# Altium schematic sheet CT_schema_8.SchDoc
size 254 x 194 mm
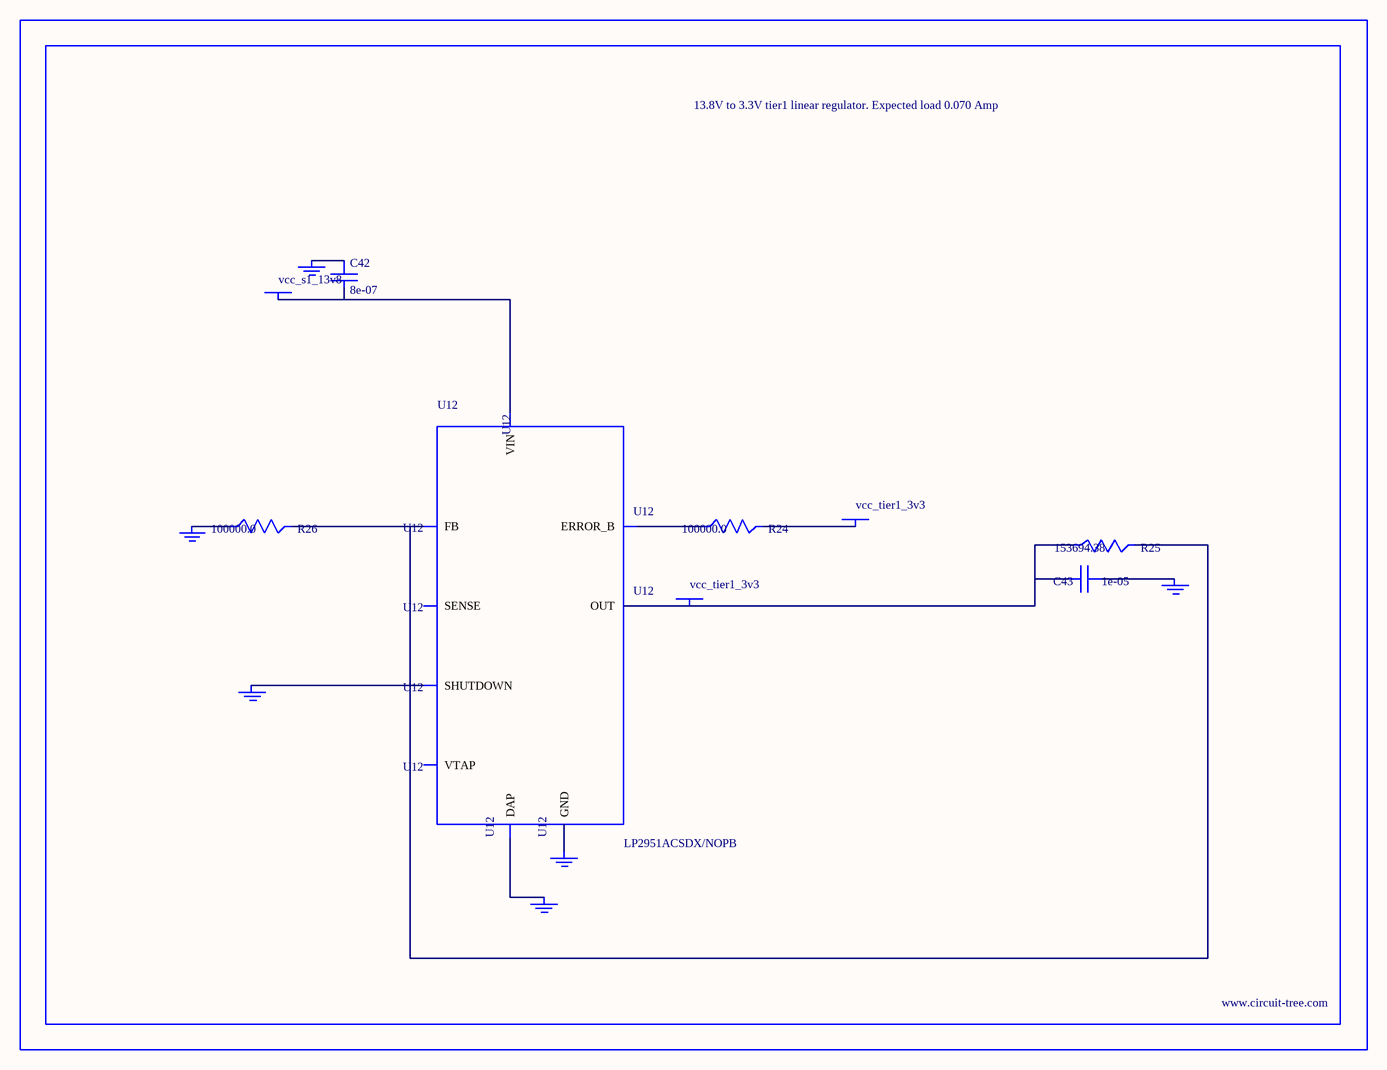
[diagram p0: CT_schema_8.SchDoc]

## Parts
BORDER7  (no value)
C42  8e-07  [R0603]
C43  1e-05  [C1210]
GND_INSTANCE_7_0  (no value)
GND_INSTANCE_7_1  (no value)
GND_INSTANCE_7_2  (no value)
GND_INSTANCE_7_3  (no value)
GND_INSTANCE_7_4  (no value)
GND_INSTANCE_7_5  (no value)
POWER_INSTANCE_7_0  vcc_tier1_3v3
POWER_INSTANCE_7_1  vcc_s1_13v8
POWER_INSTANCE_7_2  vcc_tier1_3v3
R24  100000.0  [R0603]
R25  153694.38  [R0603]
R26  100000.0  [R0603]
U12  LP2951ACSDX/NOPB  [WSON-8]

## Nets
NetC42_1: C42.1 GND_INSTANCE_7_3.0(GND)
NetC42_2: C42.2 POWER_INSTANCE_7_1.0(PWR) U12.8(VIN)
NetC43_1: C43.1 GND_INSTANCE_7_0.0(GND)
NetC43_2: C43.2 POWER_INSTANCE_7_2.0(PWR) R25.1 U12.1(OUT)
NetGND_INSTANCE_7_1_0: GND_INSTANCE_7_1.0(GND) U12.3(SHUTDOWN)
NetGND_INSTANCE_7_2_0: GND_INSTANCE_7_2.0(GND) R26.1
NetGND_INSTANCE_7_4_0: GND_INSTANCE_7_4.0(GND) U12.PAD(DAP)
NetGND_INSTANCE_7_5_0: GND_INSTANCE_7_5.0(GND) U12.4(GND)
NetPOWER_INSTANCE_7_0_0: POWER_INSTANCE_7_0.0(PWR) R24.2
NetR24_1: R24.1 U12.5(ERROR_B)
NetR25_2: R25.2 R26.2 U12.7(FB)

Not connected (* = marked no-connect by the designer): U12 2(SENSE) 6(VTAP)

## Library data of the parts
BORDER7 = BORDER_PAGE7
C42 = C42
C43 = GRM32DR61E106MA12L
GND_INSTANCE_7_0-GND_INSTANCE_7_5 = GND
POWER_INSTANCE_7_0-POWER_INSTANCE_7_2 = PWR
R24 R26 = RC0603JR-07100KL
R25 = R25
